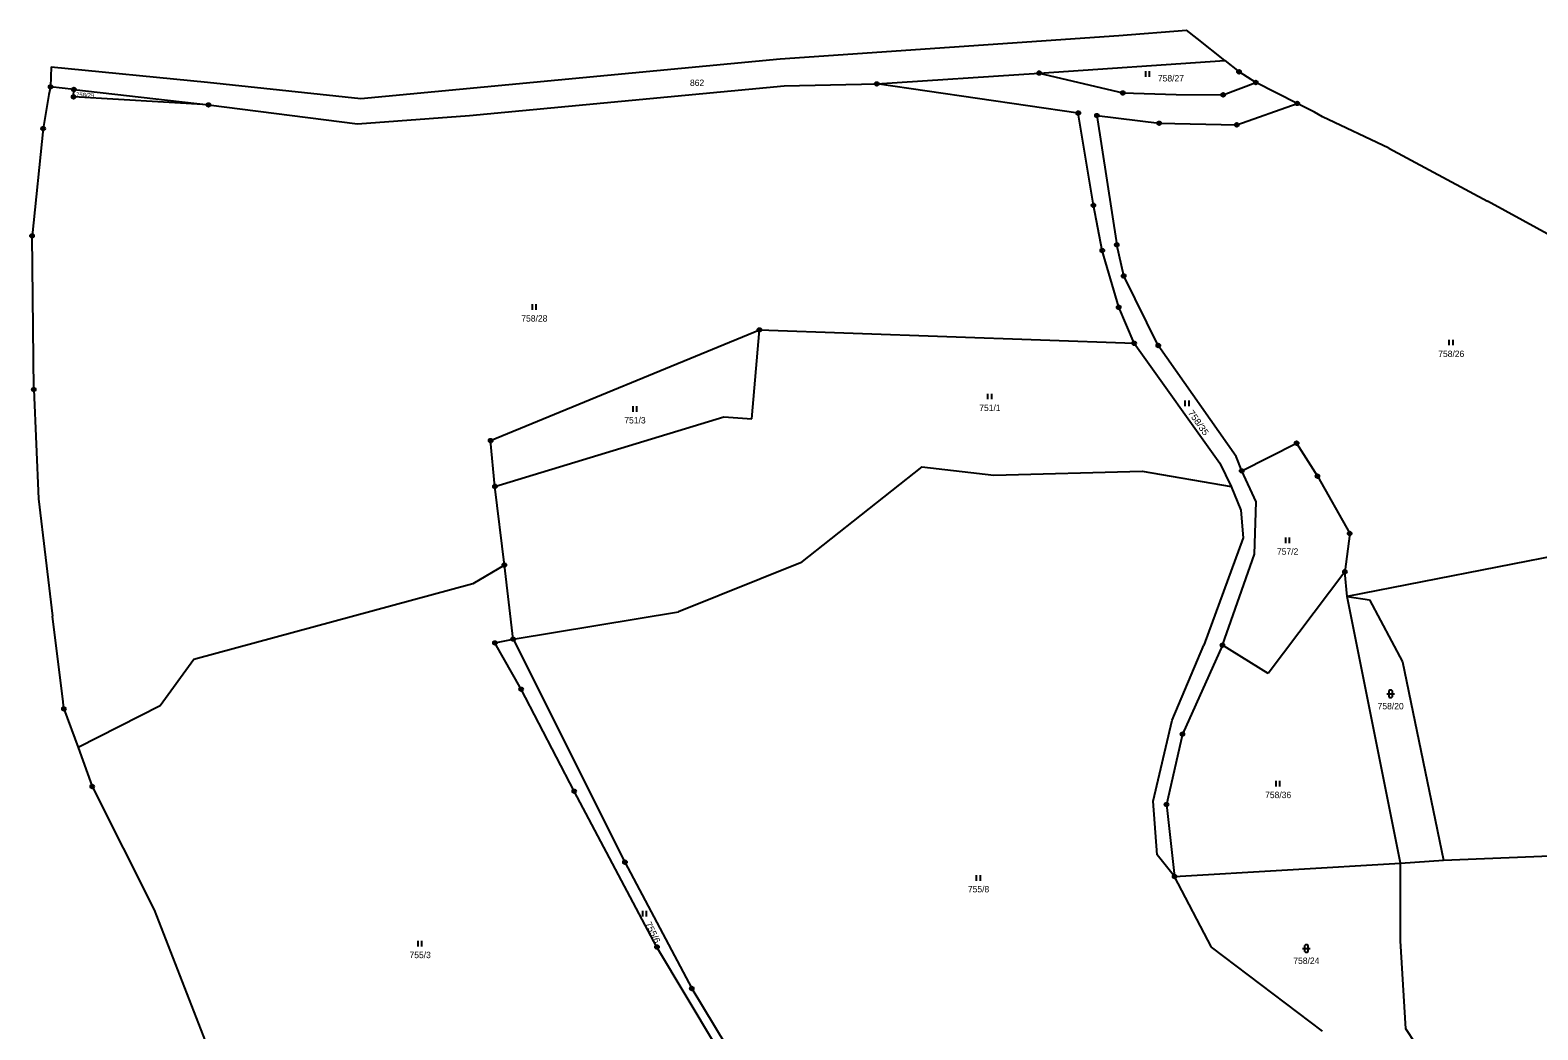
# Model space of a CAD drawing. Extents: x -739410 to -735662, y -942282 to -940043.
# Drawn here: x -738200.6 to -737798.5, y -940309.4 to -940042.8 of the extents above; entities that cross this region are included whole.
import ezdxf
from ezdxf.enums import TextEntityAlignment as Align

# ---------------------------------------------------------------- set-up
doc = ezdxf.new("R2010")
doc.units = 0
doc.header["$LTSCALE"] = 0.68
for name, color, linetype, lineweight in [('1', 7, 'Continuous', 25), ('3', 7, 'Continuous', 25), ('8', 7, 'Continuous', 25)]:
    doc.layers.add(name, color=color, linetype=linetype, lineweight=lineweight)
doc.layers.add('2', color=7, linetype='Continuous')

msp = doc.modelspace()

# ---------------------------------------------------------------- linework, layer by layer
at = {"layer": '1'}
for p, q in [((-738000.59, -940050.45), (-737910.28, -940044.17)), ((-737910.28, -940044.17), (-737892.22, -940042.78)), ((-737889.43, -940045), (-737892.22, -940042.78)), ((-737882.03, -940050.88), (-737889.43, -940045)), ((-738195.04, -940052.55), (-738195.17, -940057.89)), ((-738195.04, -940052.55), (-738153.35, -940056.65)), ((-737974.85, -940057.11), (-737931.5, -940054.22)), ((-737931.5, -940054.22), (-737882.03, -940050.88)), ((-737931.5, -940054.22), (-737909.21, -940059.53)), ((-737882.03, -940050.88), (-737878.23, -940053.9)), ((-737873.73, -940056.75), (-737878.23, -940053.9)), ((-738195.17, -940057.89), (-738195.64, -940059.98)), ((-738188.94, -940058.61), (-738195.17, -940057.89)), ((-738189.02, -940060.56), (-738188.94, -940058.61)), ((-738188.94, -940058.61), (-738153.03, -940062.71)), ((-738083.49, -940065.58), (-737999.54, -940057.6)), ((-737999.54, -940057.6), (-737974.85, -940057.11)), ((-737921.09, -940064.89), (-737974.85, -940057.11)), ((-737882.46, -940060.02), (-737873.73, -940056.75)), ((-737862.68, -940062.32), (-737873.73, -940056.75)), ((-738195.64, -940059.98), (-738197.14, -940069.04)), ((-738153.03, -940062.71), (-738189.02, -940060.56)), ((-737909.21, -940059.53), (-737895.01, -940059.93)), ((-737895.01, -940059.93), (-737882.46, -940060.02)), ((-737878.85, -940068.04), (-737862.68, -940062.32)), ((-737858.06, -940064.61), (-737862.68, -940062.32)), ((-738153.03, -940062.71), (-738113.32, -940067.76)), ((-738113.32, -940067.76), (-738083.49, -940065.58)), ((-737917.05, -940089.5), (-737921.09, -940064.89)), ((-737916.13, -940065.56), (-737899.53, -940067.6)), ((-737916.13, -940065.56), (-737910.83, -940100)), ((-737855.95, -940065.93), (-737858.06, -940064.61)), ((-737838.27, -940074.24), (-737855.95, -940065.93)), ((-738197.14, -940069.04), (-738200.12, -940097.65)), ((-737899.53, -940067.6), (-737878.85, -940068.04)), ((-737838.27, -940074.24), (-737811.92, -940088.4)), ((-737914.69, -940101.53), (-737917.05, -940089.5)), ((-737785.94, -940102.69), (-737811.92, -940088.4)), ((-738199.63, -940138.62), (-738200.12, -940097.65)), ((-737910.31, -940116.7), (-737914.69, -940101.53)), ((-737908.99, -940108.34), (-737910.83, -940100)), ((-737899.75, -940126.89), (-737908.99, -940108.34)), ((-737906.18, -940126.3), (-737910.31, -940116.7)), ((-738077.81, -940152.26), (-738006.15, -940122.73)), ((-738008.13, -940146.4), (-738006.15, -940122.73)), ((-738006.15, -940122.73), (-737906.18, -940126.3)), ((-737906.18, -940126.3), (-737883.36, -940158.29)), ((-737878.99, -940156.46), (-737899.75, -940126.89)), ((-738199.63, -940138.62), (-738198.4, -940167.78)), ((-738076.66, -940164.46), (-738015.64, -940145.95)), ((-738015.64, -940145.95), (-738008.13, -940146.4)), ((-738076.66, -940164.46), (-738077.81, -940152.26)), ((-737877.52, -940160.33), (-737862.87, -940152.94)), ((-737862.87, -940152.94), (-737857.31, -940161.74)), ((-737883.36, -940158.29), (-737880.36, -940164.5)), ((-737877.52, -940160.33), (-737878.99, -940156.46)), ((-737962.86, -940159.21), (-737995.17, -940184.87)), ((-737962.86, -940159.21), (-737943.65, -940161.43)), ((-737943.65, -940161.43), (-737904.05, -940160.36)), ((-737904.05, -940160.36), (-737880.36, -940164.5)), ((-737873.64, -940168.55), (-737877.52, -940160.33)), ((-737857.31, -940161.74), (-737848.72, -940177.02)), ((-738074.16, -940185.44), (-738076.66, -940164.46)), ((-737880.36, -940164.5), (-737877.72, -940170.77)), ((-738198.4, -940167.78), (-738194.68, -940199.09)), ((-737877.72, -940170.77), (-737877.13, -940178.18)), ((-737874.14, -940182.5), (-737873.64, -940168.55)), ((-737730.13, -940170.45), (-737849.43, -940193.84)), ((-737877.13, -940178.18), (-737887.59, -940206.78)), ((-737848.72, -940177.02), (-737849.99, -940187.21)), ((-737882.65, -940206.81), (-737874.14, -940182.5)), ((-738074.16, -940185.44), (-738082.6, -940190.43)), ((-738071.82, -940205.19), (-738074.16, -940185.44)), ((-737995.17, -940184.87), (-738027.68, -940197.95)), ((-737849.99, -940187.21), (-737870.48, -940214.4)), ((-737849.43, -940193.84), (-737849.99, -940187.21)), ((-738082.6, -940190.43), (-738156.93, -940210.62)), ((-737835.17, -940264.92), (-737849.43, -940193.84)), ((-737849.43, -940193.84), (-737843.43, -940194.72)), ((-737843.43, -940194.72), (-737834.59, -940211.27)), ((-738191.85, -940221.88), (-738194.68, -940199.09)), ((-738071.82, -940205.19), (-738027.68, -940197.95)), ((-738076.66, -940206.2), (-738071.82, -940205.19)), ((-738069.68, -940218.57), (-738076.66, -940206.2)), ((-738071.82, -940205.19), (-738041.99, -940264.68)), ((-737896.08, -940226.79), (-737887.59, -940206.78)), ((-737882.65, -940206.81), (-737893.32, -940230.53)), ((-737870.48, -940214.4), (-737882.65, -940206.81)), ((-738156.93, -940210.62), (-738165.94, -940223.01)), ((-737834.59, -940211.27), (-737823.71, -940264.13)), ((-738055.52, -940245.77), (-738069.68, -940218.57)), ((-738191.61, -940223.8), (-738191.85, -940221.88)), ((-738165.94, -940223.01), (-738187.84, -940234.13)), ((-738191.61, -940223.8), (-738187.84, -940234.13)), ((-737901.1, -940248.45), (-737896.08, -940226.79)), ((-737893.32, -940230.53), (-737897.58, -940249.33)), ((-738187.84, -940234.13), (-738184.06, -940244.51)), ((-738184.06, -940244.51), (-738167.55, -940277.41)), ((-738033.46, -940287.31), (-738055.52, -940245.77)), ((-737900.06, -940262.75), (-737901.1, -940248.45)), ((-737897.58, -940249.33), (-737895.4, -940268.5)), ((-737895.4, -940268.5), (-737900.06, -940262.75)), ((-737823.71, -940264.13), (-737795.27, -940262.97)), ((-738041.99, -940264.68), (-738024.17, -940298.37)), ((-737895.4, -940268.5), (-737835.17, -940264.92)), ((-737835.17, -940264.92), (-737823.71, -940264.13)), ((-737835.14, -940285.65), (-737835.17, -940264.92)), ((-737885.6, -940287.33), (-737895.4, -940268.5)), ((-738167.55, -940277.41), (-738153.83, -940312.62)), ((-738017.82, -940313.52), (-738033.46, -940287.31)), ((-737855.98, -940309.76), (-737885.6, -940287.33)), ((-737833.72, -940309.09), (-737835.14, -940285.65)), ((-738024.17, -940298.37), (-737979.47, -940372.15)), ((-737831.14, -940313.08), (-737833.72, -940309.09))]:
    msp.add_line(p, q, dxfattribs=at)
msp.add_lwpolyline([(-738153.35, -940056.65), (-738112.43, -940061.01), (-738000.59, -940050.45)], dxfattribs=at)
at = {"layer": '3'}
for p, q in [((-737903.101, -940055.19), (-737903.101, -940053.69)), ((-737902.1, -940055.19), (-737902.1, -940053.69)), ((-738066.661, -940117.38), (-738066.661, -940115.88)), ((-738065.66, -940117.38), (-738065.66, -940115.88)), ((-737822.141, -940126.83), (-737822.141, -940125.33)), ((-737821.14, -940126.83), (-737821.14, -940125.33)), ((-738039.831, -940144.55), (-738039.831, -940143.05)), ((-738038.83, -940144.55), (-738038.83, -940143.05)), ((-737945.181, -940141.24), (-737945.181, -940139.74)), ((-737944.18, -940141.24), (-737944.18, -940139.74)), ((-737892.561, -940143.06), (-737892.561, -940141.56)), ((-737891.56, -940143.06), (-737891.56, -940141.56)), ((-737865.781, -940179.57), (-737865.781, -940178.07)), ((-737864.78, -940179.57), (-737864.78, -940178.07)), ((-737838.291, -940219.291), (-737838.291, -940220.292)), ((-737837.289, -940220.292), (-737837.289, -940219.291)), ((-737838.791, -940219.791), (-737836.789, -940219.791)), ((-737868.301, -940244.48), (-737868.301, -940242.98)), ((-737867.3, -940244.48), (-737867.3, -940242.98)), ((-737948.201, -940269.62), (-737948.201, -940268.12)), ((-737947.2, -940269.62), (-737947.2, -940268.12)), ((-738037.261, -940279.17), (-738037.261, -940277.67)), ((-738036.26, -940279.17), (-738036.26, -940277.67)), ((-738097.121, -940287.16), (-738097.121, -940285.66)), ((-738096.12, -940287.16), (-738096.12, -940285.66)), ((-737861.271, -940287.701), (-737859.269, -940287.701)), ((-737860.771, -940287.201), (-737860.771, -940288.202)), ((-737859.769, -940288.202), (-737859.769, -940287.201))]:
    msp.add_line(p, q, dxfattribs=at)
for centre, start, end in [((-737837.79, -940219.2909), 0, 180), ((-737837.79, -940220.2909), 180, 359.98789), ((-737860.27, -940287.2009), 0, 180), ((-737860.27, -940288.2009), 180, 359.98789)]:
    msp.add_arc(centre, 0.5, start, end, dxfattribs=at)
at = {"layer": '8'}
for centre, radius in [((-737931.5, -940054.2199), 0.5), ((-737931.5, -940054.2199), 0.0303), ((-737878.23, -940053.8999), 0.5), ((-737878.23, -940053.8999), 0.0303), ((-738195.17, -940057.8899), 0.5), ((-738195.17, -940057.8899), 0.0303), ((-738188.94, -940058.6099), 0.5), ((-738188.94, -940058.6099), 0.0303), ((-737974.85, -940057.1099), 0.5), ((-737974.85, -940057.1099), 0.0303), ((-737873.73, -940056.7499), 0.5), ((-737873.73, -940056.7499), 0.0303), ((-738189.02, -940060.5599), 0.5), ((-738189.02, -940060.5599), 0.0303), ((-738153.03, -940062.7099), 0.5), ((-737909.21, -940059.5299), 0.5), ((-737909.21, -940059.5299), 0.0303), ((-737882.46, -940060.0199), 0.5), ((-737882.46, -940060.0199), 0.0303), ((-737862.68, -940062.3199), 0.5), ((-737862.68, -940062.3199), 0.0303), ((-738153.03, -940062.7099), 0.0303), ((-737921.09, -940064.8899), 0.5), ((-737921.09, -940064.8899), 0.0303), ((-737916.13, -940065.5599), 0.5), ((-737916.13, -940065.5599), 0.0303), ((-738197.14, -940069.0399), 0.5), ((-738197.14, -940069.0399), 0.0303), ((-737899.53, -940067.5999), 0.5), ((-737899.53, -940067.5999), 0.0303), ((-737878.85, -940068.0399), 0.5), ((-737878.85, -940068.0399), 0.0303), ((-737917.05, -940089.4999), 0.5), ((-737917.05, -940089.4999), 0.0303), ((-738200.12, -940097.6499), 0.5), ((-738200.12, -940097.6499), 0.0303), ((-737914.69, -940101.5299), 0.5), ((-737914.69, -940101.5299), 0.0303), ((-737910.83, -940099.9999), 0.5), ((-737910.83, -940099.9999), 0.0303), ((-737908.99, -940108.3399), 0.5), ((-737908.99, -940108.3399), 0.0303), ((-737910.31, -940116.6999), 0.5), ((-737910.31, -940116.6999), 0.0303), ((-738006.15, -940122.7299), 0.5), ((-738006.15, -940122.7299), 0.0303), ((-737906.18, -940126.2999), 0.5), ((-737906.18, -940126.2999), 0.0303), ((-737899.75, -940126.8899), 0.5), ((-737899.75, -940126.8899), 0.0303), ((-738199.63, -940138.6199), 0.5), ((-738199.63, -940138.6199), 0.0303), ((-738077.81, -940152.2599), 0.5), ((-738077.81, -940152.2599), 0.0303), ((-737862.87, -940152.9399), 0.5), ((-737862.87, -940152.9399), 0.0303), ((-737877.52, -940160.3299), 0.5), ((-737877.52, -940160.3299), 0.0303), ((-737857.31, -940161.7399), 0.5), ((-737857.31, -940161.7399), 0.0303), ((-738076.66, -940164.4599), 0.5), ((-738076.66, -940164.4599), 0.0303), ((-737848.72, -940177.0199), 0.5), ((-737848.72, -940177.0199), 0.0303), ((-738074.16, -940185.4399), 0.5), ((-738074.16, -940185.4399), 0.0303), ((-737849.99, -940187.2099), 0.5), ((-737849.99, -940187.2099), 0.0303), ((-738076.66, -940206.1999), 0.5), ((-738076.66, -940206.1999), 0.0303), ((-738071.82, -940205.1899), 0.5), ((-738071.82, -940205.1899), 0.0303), ((-737882.65, -940206.8099), 0.5), ((-737882.65, -940206.8099), 0.0303), ((-738069.68, -940218.5699), 0.5), ((-738069.68, -940218.5699), 0.0303), ((-738191.61, -940223.7999), 0.5), ((-738191.61, -940223.7999), 0.0303), ((-737893.32, -940230.5299), 0.5), ((-737893.32, -940230.5299), 0.0303), ((-738184.06, -940244.5099), 0.5), ((-738184.06, -940244.5099), 0.0303), ((-738055.52, -940245.7699), 0.5), ((-738055.52, -940245.7699), 0.0303), ((-737897.58, -940249.3299), 0.5), ((-737897.58, -940249.3299), 0.0303), ((-738041.99, -940264.6799), 0.5), ((-738041.99, -940264.6799), 0.0303), ((-737895.4, -940268.4999), 0.5), ((-737895.4, -940268.4999), 0.0303), ((-738033.46, -940287.3099), 0.5), ((-738033.46, -940287.3099), 0.0303), ((-738024.17, -940298.3699), 0.5), ((-738024.17, -940298.3699), 0.0303)]:
    msp.add_circle(centre, radius, dxfattribs=at)

# ---------------------------------------------------------------- texts
at = {"layer": '2'}
for s, p in [('862', (-738022.759, -940057.665)), ('758/27', (-737896.39, -940056.465)), ('758/28', (-738066.15, -940120.505)), ('758/26', (-737821.63, -940129.955)), ('751/1', (-737944.67, -940144.365)), ('751/3', (-738039.32, -940147.675)), ('757/2', (-737865.27, -940182.695)), ('758/20', (-737837.79, -940223.915)), ('758/36', (-737867.79, -940247.605)), ('755/8', (-737947.69, -940272.745)), ('755/3', (-738096.61, -940290.285)), ('758/24', (-737860.27, -940291.825))]:
    msp.add_text(s, height=1.7, dxfattribs=at).set_placement(p, align=Align.CENTER)
msp.add_text('758/29', height=1.14, rotation=357, dxfattribs=at).set_placement((-738185.9898, -940060.6544), align=Align.CENTER)
for s, rotation, width, p in [('758/35', 305, 1.1, (-737889.7241, -940147.9615)), ('755/6', 296, 1.05, (-738035.2894, -940283.7854))]:
    msp.add_text(s, height=1.7, rotation=rotation, dxfattribs=dict(at, width=width)).set_placement(p, align=Align.CENTER)

doc.saveas('drawing.dxf')
